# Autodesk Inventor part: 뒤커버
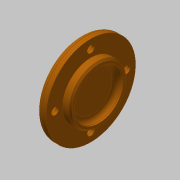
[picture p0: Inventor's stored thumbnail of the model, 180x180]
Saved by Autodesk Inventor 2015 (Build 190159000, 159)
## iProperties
Created: 2019-06
Part Number: 뒤커버
Material: 알루미늄 6061
Document SubType Name: Modeling
Designer: mduedu
Density: 2.71 g/cm^3
Appearance: 주황색
Mass: 40.7816 g
Surface Area: 66.9571 cm^2
Volume: 15.0486 cm^3
Author: mduedu
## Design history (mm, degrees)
sketch "스케치1"
  geometry: L1 (0, 0)-(-5, 0); L2 (-5, 0)-(-5, 17.5); L3 (-5, 17.5)-(0, 17.5); L4 (0, 17.5)-(0, 0); L5 (-5, 0)-(-11, 0); L6 (-11, 0)-(-11, 27.5); L7 (-11, 27.5)-(-5, 27.5); L8 (-5, 27.5)-(-5, 0)
  constraints: 16 end point, 4 parallel, 2 horizontal, 2 perpendicular
  dimensions: "d0" = 11 distance between parallel lines of L4 L6; "d2" = 5 distance of L2.end L3.end; "d3" = 55 diameter of L7 L5; "d4" = 35 diameter of L3 L1
revolve "회전1" sketch "스케치1" stored, may be unused: angle "d5" = 90 deg
sketch "스케치2"
  geometry: C1 r 15 at (0, 0); 1 further point
  constraints: 1 centre point, 1 coincident
  dimensions: "d6" = 30 diameter of C1
extrude "돌출1" cut sketch "스케치2" distance "d7" = 4; taper "d8" = 0 deg
fillet "모깎기1" dims "d9" = 3
fillet "모깎기2" dims "d10" = 3
chamfer "모따기1" distance "d11" = 1; stored, may be unused: second distance "d12" = 2, angle "d13" = 45 deg
sketch "스케치3" dims "d14" = 44
  geometry: 3 further points
  constraints: 2 vertical alignment, 1 coincident, 2 other
hole "구멍1" sketch "스케치3" at (0, 22) diameter "d15" = 4.5; stored, may be unused: countersink angle "d19" = 90 deg, drill point angle "d21" = 118 deg; dims "d16" = 6, "d17" = 8, "d18" = 4.4, "d20" = 8
node "솔리드1"
pattern_circular "원형 패턴1" dims angle "d23" = 360 deg
